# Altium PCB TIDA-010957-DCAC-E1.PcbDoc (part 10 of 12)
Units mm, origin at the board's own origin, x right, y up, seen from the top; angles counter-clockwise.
Board outline 300 x 300 mm, 4 copper layers (Top Layer, Layer 1, Layer 2, Bottom Layer), stack 1.787 mm thick; 1159 components, 619 nets, 3431 pads, 2942 vias.
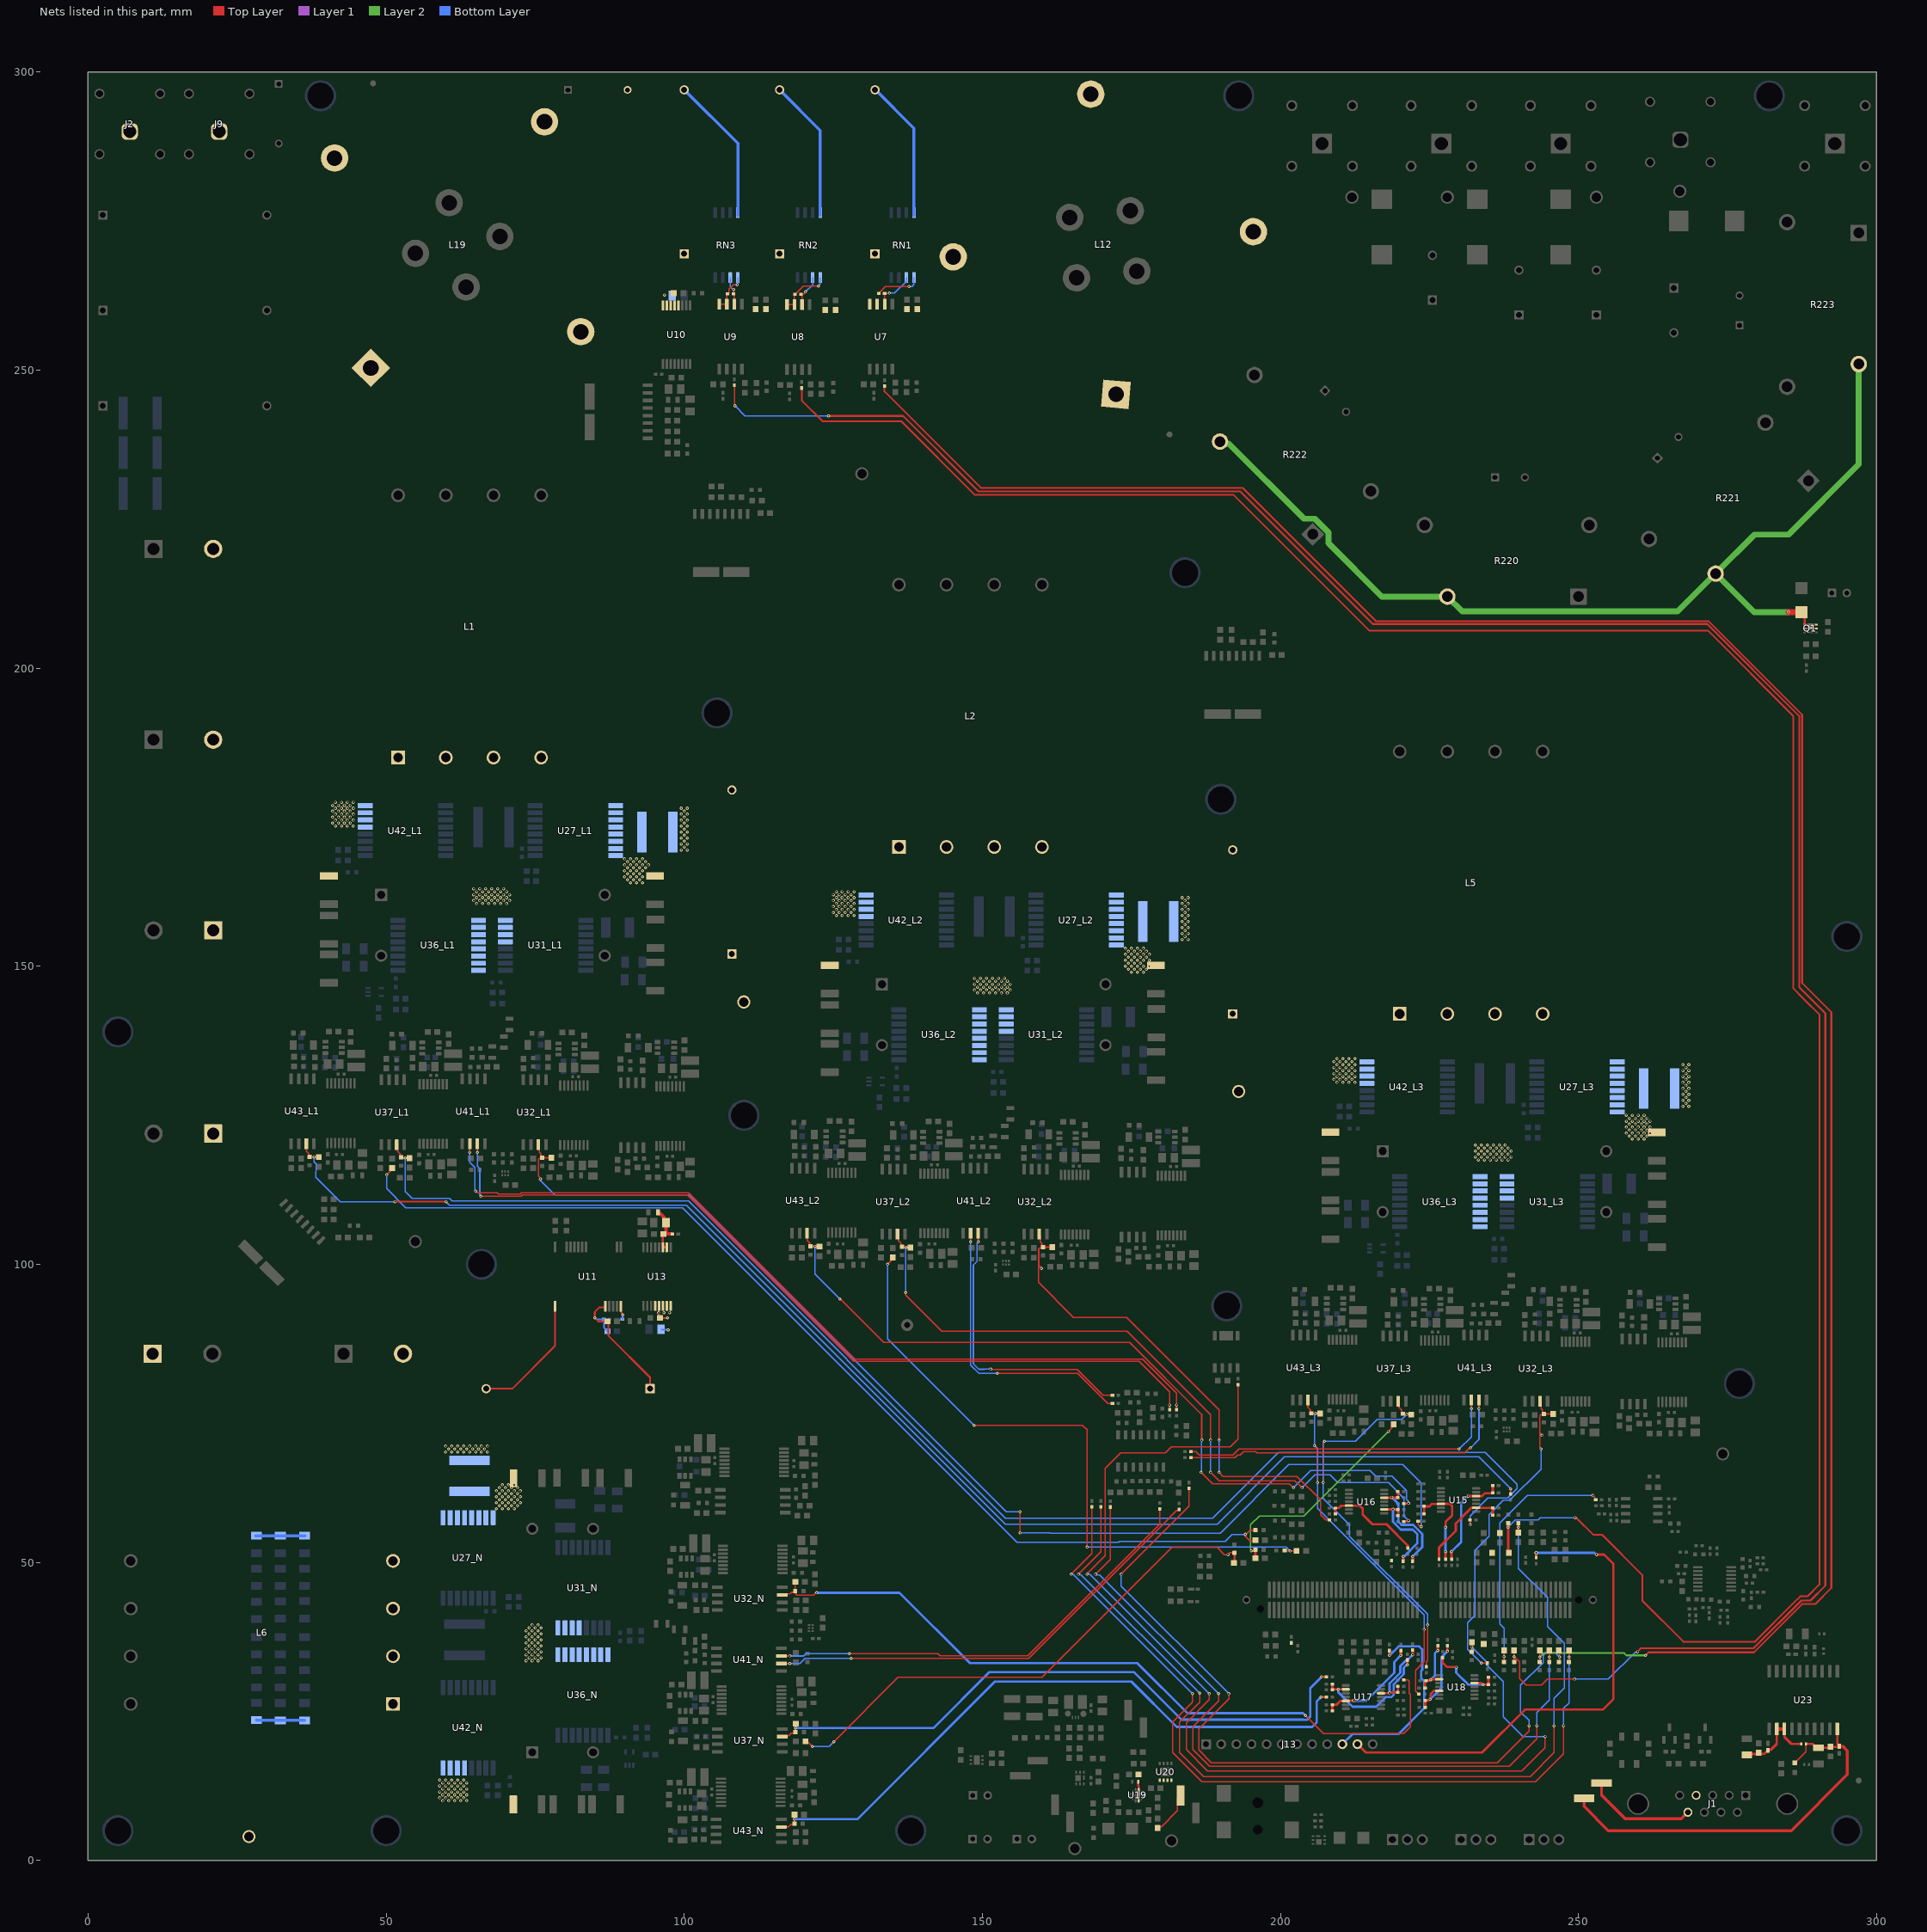
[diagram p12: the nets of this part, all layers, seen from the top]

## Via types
v1: diameter 0.508, hole 0.254, Top Layer to Bottom Layer, tented both sides, 2942 vias

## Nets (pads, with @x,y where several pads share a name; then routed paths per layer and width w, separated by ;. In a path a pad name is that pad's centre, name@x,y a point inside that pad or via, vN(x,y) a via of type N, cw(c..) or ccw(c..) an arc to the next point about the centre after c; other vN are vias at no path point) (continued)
PWM_S2_GaN_BUF_L1: C205_L1.2 R166.2 R295_L1.2 U32_L1.3 | length 197.4
  Top Layer w0.2: v1(75.9,114.3) 75.9,114.411 75.53,114.781 75.53,117.63 75.7,117.8 76.1,117.8 C205_L1.2@76.18,117.88 ; v1(156.3,58.5) 156.33,58.47 156.33,54.995 v1(156.359,54.965) ; R166.2@223.1,56.9 223.1,56.317 223.217,56.2 223.289,56.2 223.489,56 v1(223.6,56)
  Top Layer w0.254: U32_L1.3@75.545,120.05 75.718,119.877 75.718,118.794 75.957,118.555 75.957,118.103 C205_L1.2@76.18,117.88 77.733,117.88 R295_L1.2@77.75,117.863
  Bottom Layer w0.2: 75.6,114.3 78.3,111.6 100.9,111.6 154,58.5 v1(156.3,58.5) ; v1(156.359,54.965) 161.335,54.965 161.4,54.9 189.9,54.9 201.4,66.4 220.5,66.4 223.6,63.3 v1(223.6,56)
PWM_S2_GaN_BUF_L2: C205_L2.2 R178.2 R295_L2.2 U32_L2.3 | length 86.8
  Top Layer w0.2: 159.435,102.635 159.435,96.965 165.3,91.1 174.2,91.1 189.7,75.6 v1(189.7,70.5) ; v1(159.9,99.3) 159.9,99.411 159.53,99.781 159.53,102.63 159.7,102.8 160.1,102.8 C205_L2.2@160.18,102.88 ; v1(189.7,65.1) 190.4,64.4 202.8,64.4 206.7,60.5 206.7,58 207.6,57.1 R178.2@208.2,57.1
  Top Layer w0.254: U32_L2.3@159.545,105.05 159.718,104.877 159.718,103.794 159.957,103.555 159.957,103.103 C205_L2.2@160.18,102.88 161.733,102.88 R295_L2.2@161.75,102.863
  Bottom Layer w0.2: v1(189.7,65.1) v1(189.7,70.5)
PWM_S2_GaN_BUF_L3: C205_L3.2 R196.2 R295_L3.2 U32_L3.3 | length 57.6
  Top Layer w0.2: v1(233.7,33.1) R196.2@234.7,33.1 ; v1(243.7,69) 243.7,69.111 243.53,69.281 243.53,74.63 ; v1(243.9,71.3) 243.9,71.411 243.53,71.781 243.53,74.63 ; C205_L3.2@244.18,74.88 244.1,74.8 243.7,74.8 243.53,74.63
  Top Layer w0.254: U32_L3.3@243.545,77.05 243.718,76.877 243.718,75.794 243.957,75.555 243.957,75.103 C205_L3.2@244.18,74.88 245.733,74.88 R295_L3.2@245.75,74.863
  Bottom Layer w0.2: v1(233.7,33.1) 231.383,35.417 231.383,39.883 232.6,41.1 232.6,52 234.975,54.375 234.975,57.975 237.4,60.4 238.5,60.4 243.7,65.6 v1(243.7,69)
PWM_S2_GaN_BUF_N: C205_N.2 R179.2 R295_N.2 U32_N.3 | length 127.1
  Top Layer w0.2: C205_N.2@118.62,45.18 118.7,45.1 118.7,44.7 118.87,44.53 121.719,44.53 122.089,44.9 v1(122.2,44.9) ; v1(204.2,24.3) 207.239,21.261 220.661,21.261 221.6,22.2 221.6,22.234 221.805,22.439 221.805,27.851 221.6,28.055 221.6,30.1 221.4,30.3 R179.2@220.7,30.3
  Top Layer w0.254: U32_N.3@116.45,44.545 116.623,44.718 117.706,44.718 117.945,44.957 118.397,44.957 C205_N.2@118.62,45.18 118.62,46.733 R295_N.2@118.637,46.75
  Top Layer w0.4: R179.2@220.7,30.3 220.75,30.25 R179.2@220.866,30.25
  Bottom Layer w0.4: v1(122.2,44.9) 136.1,44.9 147.9,33.1 176,33.1 184.4,24.7 203.8,24.7 v1(204.2,24.3)
PWM_S2_GaN_L1: C110.1 R47.1 R171.2 U15.5 | length 15.5
  Top Layer w0.4: C110.1@224.1,58.15 224.1,59.35 224.15,59.4 225,59.4 225.4,59.8 U15.5@226.9,59.8 ; U15.5@227.102,59.802 228.464,59.802 228.8,59.466 228.8,57.9 227.705,56.805 227.705,55.905 v1(227.7,55.9) ; R47.1@227.7,50.5 v1@227.7,51.8
  Bottom Layer w0.4: v1(227.688,51.796) 227.694,51.802 227.694,55.894 v1(227.7,55.9)
PWM_S2_GaN_L2: C117.1 R55.1 R186.2 U16.5 | length 16.1
  Top Layer w0.4: R186.2@209.2,58.1 C117.1@209.2,59.1 209.25,59.15 209.85,59.15 210.2,59.5 U16.5@211,59.5 ; U16.5@212,59.5 213.3,59.5 213.8,59 213.8,58 215.4,56.4 217.8,56.4 221.35,52.85 221.35,52.45 R55.1@221.4,52.4
PWM_S2_GaN_L3: C128.1 R48.1 R201.2 U18.5 | length 13.3
  Top Layer w0.4: R48.1@227.2,34 227.2,33.2 227.96,32.44 229.46,32.44 v1(229.5,32.4) ; U18.5@232.55,29.75 233.65,29.75 233.9,29.5 v1(234,29.5) R201.2@234.9,29.5 ; R201.2@234.9,29.6 C128.1@234.9,30.7
  Bottom Layer w0.4: v1(229.5,32.4) 229.505,32.395 229.505,31.495 231.5,29.5 v1@234.1,29.5
PWM_S2_GaN_N: C122.1 R54.1 R191.2 U17.5 | length 12.9
  Top Layer w0.4: U17.5@216.866,28.052 218.252,28.052 218.4,28.2 R191.2@219.7,28.2 219.7,29.15 219.75,29.2 C122.1@219.8,29.2 ; v1(222.2,34.5) R54.1@222.2,35.3
  Bottom Layer w0.4: v1(218.3,28.1) 218.3,29.7 220.1,31.5 220.1,32.6 221.3,33.8 221.5,33.8 v1(222.2,34.5)
PWM_S3_GaN_A: J13.10 R61.1 | length 33.5
  Top Layer w0.4: v1(218.3,34.4) R61.1@218.3,35.2
  Bottom Layer w0.4: J13.10@210.39,19.5 212.09,21.2 219.8,21.2 224.105,25.505 224.105,30.095 223.6,30.6 223.6,31.744 223.805,31.948 223.805,35.395 223.3,35.9 219.8,35.9 v1(218.3,34.4)
PWM_S3_GaN_B: R80.1
PWM_S3_GaN_BUF_L1: C231_L1.2 R167.2 R305_L1.2 U37_L1.3 | length 238.4
  Top Layer w0.2: v1(231.8,56.3) R167.2@231.8,57.1
  Top Layer w0.254: U37_L1.3@51.764,120.05 51.913,119.901 51.913,118.969 52.361,118.521 52.361,118.001 52.528,117.834 v1(53.204,117.834) 53.879,117.834 R305_L1.2@53.929,117.784
  Bottom Layer w0.2: v1(53.204,117.834) 53.204,112.196 54.346,111.054 60.641,111.054 61.095,110.6 100.7,110.6 153.9,57.4 188.6,57.4 199.644,68.444 234.356,68.444 239.7,63.1 239.7,62.4 238.1,60.8 234.8,60.8 231.8,57.8 v1(231.8,56.3)
PWM_S3_GaN_BUF_L2: C231_L2.2 R180.2 R305_L2.2 U37_L2.3 | length 122.2
  Top Layer w0.2: v1(137.147,95.263) 137.147,94.822 143.185,88.784 174.316,88.784 188.3,74.8 v1(188.3,70.5) ; v1(188.3,65.1) 189.7,63.7 202.4,63.7 v1(203.6,62.5)
  Top Layer w0.254: U37_L2.3@135.764,105.05 135.913,104.901 135.913,103.969 136.361,103.521 136.361,103.001 136.528,102.834 v1(137.204,102.834) 137.879,102.834 R305_L2.2@137.929,102.784
  Top Layer w0.4: R180.2@220.7,56.85 220.75,56.9 221.3,56.9 v1@221.5,57.1
  Bottom Layer w0.2: v1(137.147,95.263) 137.175,95.292 137.175,102.805 v1(137.204,102.834) ; v1(188.3,65.1) v1(188.3,70.5) ; v1(203.6,62.5) 205.8,64.7 208.312,64.7 209.637,63.375 218.125,63.375 220.75,60.75 220.75,57.75 v1(221.5,57)
PWM_S3_GaN_BUF_L3: C231_L3.2 R197.2 R305_L3.2 U37_L3.3 | length 64.9
  Top Layer w0.2: R197.2@224.5,32.5 224.5,33.289 224.7,33.489 224.7,39.495 v1(224.705,39.5)
  Top Layer w0.254: U37_L3.3@219.764,77.05 219.913,76.901 219.913,75.969 220.361,75.521 220.361,75.001 220.528,74.834 v1(221.204,74.834) 221.879,74.834 R305_L3.2@221.929,74.784
  Layer 1 w0.2: v1(207.2,63.385) 207.2,70.1 v1(207.4,70.3)
  Bottom Layer w0.2: v1(207.2,63.385) 207.2,60.7 211.595,56.305 211.595,54.405 224.7,41.3 224.7,39.505 v1(224.705,39.5) ; v1(207.4,70.3) 212.541,70.3 216.228,73.987 220.358,73.987 v1(221.204,74.834)
PWM_S3_GaN_BUF_N: C231_N.2 R181.2 R305_N.2 U37_N.3 | length 106
  Top Layer w0.254: U37_N.3@116.45,20.764 116.599,20.913 117.531,20.913 117.979,21.361 118.499,21.361 C231_N.2@118.666,21.528 v1(118.666,22.204) 118.666,22.879 R305_N.2@118.716,22.929
  Top Layer w0.4: v1(206.9,30.8) R181.2@207.7,30.8
  Bottom Layer w0.4: v1(118.666,22.204) 141.804,22.204 151.2,31.6 175.4,31.6 183.4,23.6 203.903,23.6 203.908,23.595 204.492,23.595 204.497,23.6 204.5,23.6 205,24.1 205,28.9 v1(206.9,30.8)
PWM_S3_GaN_L1: C111.1 R49.1 R172.2 U15.9 | length 15.2
  Top Layer w0.4: R49.1@226.6,50.5 226.6,52.5 229.4,55.3 229.4,56.523 232.054,59.177 U15.9@232.2,59.177 ; U15.9@232.821,59.152 U15.9@232.821,59.152 C111.1@235.6,59.15 ; C111.1@235.6,59.15 235.6,57.95 235.65,57.9 R172.2@235.7,57.9
PWM_S3_GaN_L2: C118.1 R57.1 R187.2 U16.9 | length 15.8
  Top Layer w0.4: U16.9@217.398,58.875 C118.1@219.625,58.875 ; R187.2@219.7,57.9 C118.1@219.7,58.85 ; R57.1@220.6,50.2 v1(220.6,51)
  Bottom Layer w0.4: v1@218.9,58.9 218.888,58.888 218.888,56.812 220.2,55.5 222.2,55.5 222.95,54.75 222.95,53.19 220.799,51.04 220.64,51.04 v1(220.6,51)
  other v1: 218.888,58.896
PWM_S3_GaN_L3: C129.1 R50.1 R202.2 U18.9 | length 10
  Top Layer w0.4: C129.1@224.25,28.9 224.25,29.866 224.35,29.966 224.35,30.1 224.4,30.15 R202.2@224.45,30.15 224.5,30.2 225.1,30.2 v1(225.2,30.3) 225.3,30.4 U18.9@226.65,30.4 U18.9@226.7,30.4 ; v1(226.4,35.2) R50.1@226.4,36.1
  Bottom Layer w0.4: v1(225.2,30.3) 225.9,31 225.9,34.7 v1(226.4,35.2)
PWM_S3_GaN_N: C123.1 R56.1 R192.2 U17.9 | length 21.7
  Top Layer w0.4: C123.1@208.7,28.6 R192.2@208.7,29.6 ; C123.1@208.701,28.701 v1(209.7,28.7) U17.9@210.966,28.702 U17.9@210.966,28.702 ; v1(221.3,32.8) R56.1@221.3,33.6
  Bottom Layer w0.4: v1(209.7,28.7) 209.7,28.2 212.1,25.8 216.05,25.8 217.645,27.395 218.592,27.395 219.005,27.808 219.005,29.556 220.7,31.251 220.7,32.351 v1@221.224,32.876
PWM_S4_GaN_A: J13.11 R25.1 | length 84.5
  Top Layer w0.4: J13.11@212.93,19.5 214.33,18.1 233.8,18.1 241,25.3 254.1,25.3 255.86,27.06 255.86,49.74 254.3,51.3 v1(253,51.3) ; R25.1@242.9,50.8 v1(242.9,51.6)
  Bottom Layer w0.4: v1@242.803,51.6 252.661,51.6 252.961,51.3 v1(253,51.3)
PWM_S4_GaN_B: R60.1
PWM_S4_GaN_BUF_L1: C248_L1.2 R168.2 R322_L1.2 U43_L1.3 | length 239.8
  Top Layer w0.2: R168.2@238.6,61.5 v1(238.6,62.3)
  Top Layer w0.254: U43_L1.3@36.613,120.226 36.613,119.011 37.045,118.58 37.045,118.14 C248_L1.2@37.175,118.009 v1(37.916,118.009) 38.656,118.009 R322_L1.2@38.685,117.98 ; v1(51.5,110.5) v1(60.066,110.5)
  Bottom Layer w0.2: v1(37.916,118.009) 37.916,117.2 38.309,116.807 38.309,115.71 38.226,115.627 38.226,114.579 42.305,110.5 v1(51.5,110.5) ; v1(60.066,110.5) 60.666,109.9 100.4,109.9 153.9,56.4 189.4,56.4 200.7,67.7 233.255,67.7 238.6,62.355 v1(238.6,62.3)
PWM_S4_GaN_BUF_L2: C248_L2.2 R182.2 R322_L2.2 U43_L2.3 | length 134.3
  Top Layer w0.2: v1(186.7,65.1) 188.6,63.2 201.5,63.2 v1(202.2,62.5)
  Top Layer w0.254: U43_L2.3@120.613,105.226 120.613,104.011 121.045,103.58 121.045,103.14 C248_L2.2@121.175,103.009 v1(121.916,103.009) 122.656,103.009 R322_L2.2@122.685,102.98 ; v1(126.1,94.2) 126.156,94.2 133.456,86.9 174.704,86.9 186.8,74.804 v1(186.8,70.5)
  Top Layer w0.4: R182.2@220.7,59.85 221.55,59.85 v1@221.6,59.9
  Bottom Layer w0.2: v1(121.916,103.009) 121.916,98.384 v1(126.1,94.2) ; v1(186.7,65.1) 186.75,65.15 186.75,70.45 v1(186.8,70.5) ; v1(202.2,62.5) 205.1,65.4 215.05,65.4 215.955,64.495 218.705,64.495 221.192,62.008 221.192,60.508 221.444,60.256 221.444,59.956 v1(221.5,59.9)
PWM_S4_GaN_BUF_L3: C248_L3.2 R198.2 R322_L3.2 U43_L3.3 | length 59.6
  Top Layer w0.2: R198.2@223.2,27.9 223.15,27.9 222.65,28.4 222.65,31.91 224.095,33.355 v1(224.095,38.7)
  Top Layer w0.254: U43_L3.3@204.613,77.226 204.613,76.011 205.045,75.58 205.045,75.14 C248_L3.2@205.175,75.009 v1(205.916,75.009) 206.656,75.009 R322_L3.2@206.685,74.98
  Layer 1 w0.2: v1(205.7,69.6) 206.203,69.097 v1(206.203,63.4)
  Bottom Layer w0.2: v1(205.7,69.6) 205.729,69.629 205.729,74.739 205.916,74.925 v1(205.916,75.009) ; v1@206.2,63.397 206.2,59.055 224.095,41.16 v1(224.095,38.7)
PWM_S4_GaN_BUF_N: C248_N.2 R183.2 R322_N.2 U43_N.3 | length 110
  Top Layer w0.254: U43_N.3@116.274,5.613 117.489,5.613 117.92,6.045 118.36,6.045 C248_N.2@118.491,6.175 v1(118.491,6.916) 118.491,7.656 R322_N.2@118.52,7.685
  Top Layer w0.4: v1(206.8,27.4) R183.2@207.7,27.4
  Bottom Layer w0.4: v1(118.491,6.916) 129.016,6.916 152.1,30 175,30 182.6,22.4 205.3,22.4 206.1,23.2 206.1,26.7 v1(206.8,27.4)
PWM_S4_GaN_L1: C112.1 R45.1 R173.2 U15.12 | length 17.5
  Top Layer w0.4: R45.1@228.7,50.5 v1@228.7,51.9 ; v1(231.5,61.1) 231.501,61.101 U15.12@232.821,61.102 232.831,61.111 233.811,61.111 234.3,61.6 C112.1@235.6,61.6 ; C112.1@235.6,61.65 R173.2@235.6,62.9
  Bottom Layer w0.4: v1(228.688,51.796) 230.327,53.435 230.327,60.027 v1@231.5,61.2
PWM_S4_GaN_L2: C119.1 R53.1 R188.2 U16.12 | length 17.9
  Top Layer w0.4: U16.12@217.398,60.825 217.408,60.835 R188.2@219.635,60.835 ; C119.1@219.6,61.9 219.7,61.8 R188.2@219.7,60.85 ; R53.1@222.2,50.2 v1(222.2,51)
  Bottom Layer w0.4: v1@218.7,60.9 218.7,60.883 219.8,59.783 219.8,56.8 220.3,56.3 222.249,56.3 223.771,54.777 223.771,52.572 v1(222.2,51)
  other v1: 218.688,60.896
PWM_S4_GaN_L3: C130.1 R46.1 R203.2 U18.12 | length 14.6
  Top Layer w0.4: R203.2@224.294,26.83 224.344,26.88 224.944,26.88 v1@225.194,27.13 ; C130.1@224.3,25.9 R203.2@224.3,26.824 ; v1@225.2,27.1 225.2,27.886 225.755,28.44 226.64,28.44 U18.12@226.65,28.45 ; v1(228,35.1) R46.1@228,36
  Bottom Layer w0.4: v1@225.1,27 227,28.9 227,34.1 v1(228,35.1)
  other v1: 225.094,27.03
PWM_S4_GaN_N: C124.1 R58.1 R193.2 U17.12 | length 17.1
  Top Layer w0.4: C124.1@208.7,25.2 R193.2@208.7,26.1 209.4,26.1 210.043,26.743 210.957,26.743 U17.12@210.966,26.752 ; U17.12@211.6,26.777 212.277,26.777 v1(212.3,26.8) ; v1(220.2,34.4) R58.1@220.2,35.2
  Bottom Layer w0.4: v1(212.3,26.8) 214.414,26.8 219.1,31.486 219.1,33.3 v1(220.2,34.4)
SN_L1: L1.1 L1.2 L1.3 L1.4 U31_L1.13 U31_L1.14 U31_L1.15 U31_L1.16 U36_L1.1 U36_L1.2 U36_L1.3 U36_L1.4 U36_L1.5 U36_L1.6 U36_L1.7 U36_L1.8
  other v1: 65.2,160.5 66.2,160.5 67.2,160.5 68.2,160.5 69.2,160.5 70.2,160.5 64.7,161 65.7,161 66.7,161 67.7,161 68.7,161 69.7,161 70.7,161 65.2,161.5 66.2,161.5 67.2,161.5 68.2,161.5 69.2,161.5 70.2,161.5 64.7,162 65.7,162 66.7,162 67.7,162 68.7,162 69.7,162 70.7,162 65.2,162.5 66.2,162.5 67.2,162.5 68.2,162.5 69.2,162.5 70.2,162.5 64.7,163 65.7,163 66.7,163 67.7,163 68.7,163 69.7,163
SN_L2: L2.1 L2.2 L2.3 L2.4 U31_L2.13 U31_L2.14 U31_L2.15 U31_L2.16 U36_L2.1 U36_L2.2 U36_L2.3 U36_L2.4 U36_L2.5 U36_L2.6 U36_L2.7 U36_L2.8
  other v1: 149.2,145.5 150.2,145.5 151.2,145.5 152.2,145.5 153.2,145.5 154.2,145.5 148.7,146 149.7,146 150.7,146 151.7,146 152.7,146 153.7,146 154.7,146 149.2,146.5 150.2,146.5 151.2,146.5 152.2,146.5 153.2,146.5 154.2,146.5 148.7,147 149.7,147 150.7,147 151.7,147 152.7,147 153.7,147 154.7,147 149.2,147.5 150.2,147.5 151.2,147.5 152.2,147.5 153.2,147.5 154.2,147.5 148.7,148 149.7,148 150.7,148 151.7,148 152.7,148 153.7,148
SN_L3: L5.1 L5.2 L5.3 L5.4 U31_L3.13 U31_L3.14 U31_L3.15 U31_L3.16 U36_L3.1 U36_L3.2 U36_L3.3 U36_L3.4 U36_L3.5 U36_L3.6 U36_L3.7 U36_L3.8
  other v1: 233.2,117.5 234.2,117.5 235.2,117.5 236.2,117.5 237.2,117.5 238.2,117.5 232.7,118 233.7,118 234.7,118 235.7,118 236.7,118 237.7,118 238.7,118 233.2,118.5 234.2,118.5 235.2,118.5 236.2,118.5 237.2,118.5 238.2,118.5 232.7,119 233.7,119 234.7,119 235.7,119 236.7,119 237.7,119 238.7,119 233.2,119.5 234.2,119.5 235.2,119.5 236.2,119.5 237.2,119.5 238.2,119.5 232.7,120 233.7,120 234.7,120 235.7,120 236.7,120 237.7,120
SN_LN: L6.1 L6.2 L6.3 L6.4 U31_N.13 U31_N.14 U31_N.15 U31_N.16 U36_N.1 U36_N.2 U36_N.3 U36_N.4 U36_N.5 U36_N.6 U36_N.7 U36_N.8
  other v1: 73.5,33.5 74.5,33.5 75.5,33.5 74,34 75,34 76,34 73.5,34.5 74.5,34.5 75.5,34.5 74,35 75,35 76,35 73.5,35.5 74.5,35.5 75.5,35.5 74,36 75,36 76,36 73.5,36.5 74.5,36.5 75.5,36.5 74,37 75,37 76,37 73.5,37.5 74.5,37.5 75.5,37.5 74,38 75,38 76,38 73.5,38.5 74.5,38.5 75.5,38.5 74,39 75,39 76,39 74.5,39.5 75.5,39.5
SN_Relays: D3.2 Q1.1 Q1.2 Q1.5 Q1.6 Q1.8 R220.2 R221.2 R222.2 R223.2 | length 169.1
  Top Layer w0.3: Q1.2@287.93,206.65 288.58,206.65 Q1.8@288.905,206.975 ; D3.2@287.93,208.7 Q1.1@287.93,207.3 288.58,207.3 Q1.8@288.905,206.975 ; Q1.8@289.15,206.65 Q1.5@289.88,206.65 ; Q1.6@289.8,207.3 289.23,207.3 Q1.8@288.905,206.975
  Top Layer w1: v1(285.2,209.4) D3.2@287.1,209.4
  Layer 2 w1: R222.2@189.863,238.005 190.198,237.67 191.33,237.67 203.929,225.071 205.732,225.071 208.041,222.762 208.041,220.959 217,212 R220.2@228,212 230.5,209.5 266.632,209.5 R221.2@272.995,215.863 ; v1(285.2,209.4) 279.458,209.4 R221.2@272.995,215.863 ; R223.2@296.9,250.9 297,250.8 297,234.2 285.2,222.4 279.532,222.4 R221.2@272.995,215.863
T_HEATSINK_DCAC: C14.1 R19.1 R42.1 | length 181.3
  Top Layer w0.2: v1@167.535,48.035 170.6,51.1 170.6,65.8 173.2,68.4 180.7,68.4 181.7,69.4 191.6,69.4 192.9,70.7 R19.1@192.9,79.8 ; v1(188.044,27.956) 188.044,26.944 184.2,23.1 184.2,18.6 187.8,15 240.5,15 244.4,18.9 v1(244.4,20.805) ; C14.1@232.1,35 v1(232.1,35.8) R42.1@232.1,36.6
  Bottom Layer w0.2: v1(167.543,48.026) 167.555,48.014 167.986,48.014 v1(188.044,27.956) ; v1(232.1,35.8) 234.495,33.405 234.495,32.905 237.405,29.995 237.405,24.095 240.695,20.805 v1(244.4,20.805)
TEMP_S3_GaN_ISO_L1: C230_L1.2 R74.2 R302_L1.1 | length 177.4
  Top Layer w0.2: v1(50.1,115) 50.911,115.811 50.911,116.066 R302_L1.1@51,116.155 ; R74.2@195.789,53.441 195.63,53.6 194.9,53.6 194.142,54.358 194.142,54.658 v1(194.1,54.7) 194.183,54.7 194.883,55.4 C230_L1.2@195.89,55.4
  Bottom Layer w0.2: v1(50.1,115) 50.1,112.7 53.3,109.5 99.7,109.5 155.805,53.395 172.872,53.395 172.977,53.5 190.7,53.5 191.9,54.7 v1(194.1,54.7)
TEMP_S3_GaN_ISO_L2: C230_L2.2 R75.2 R302_L2.1 | length 109.8
  Top Layer w0.2: v1(134.1,100) 134.911,100.811 134.911,101.066 R302_L2.1@135,101.155 ; v1(148.625,72.987) 166.813,72.987 167.561,72.239 v1(167.561,52.54) ; C230_L2.2@200.7,51.9 v1(201.6,51.9) R75.2@202.7,51.9
  Bottom Layer w0.2: v1(134.1,100) 134.1,87.512 v1(148.625,72.987) ; v1(167.561,52.54) 189.157,52.54 189.175,52.558 200.942,52.558 v1(201.6,51.9)
TEMP_S3_GaN_ISO_L3: C230_L3.2 R76.2 R302_L3.1 | length 37.5
  Top Layer w0.2: v1(195.09,51.924) 195.691,51.924 C230_L3.2@195.786,52.019 ; v1(218.1,72) 218.911,72.811 218.911,73.066 R302_L3.1@219,73.155
  Top Layer w0.4: R76.2@195.8,50.7 C230_L3.2@195.8,51.9
  Layer 2 w0.2: v1(195.09,51.924) 195.031,51.983 195.031,52.164 195,52.195 195,56.3 196.463,57.763 203.918,57.763 218.1,71.945 v1(218.1,72)
TEMP_S3_GaN_ISO_N: C230_N.2 R77.2 R302_N.1 | length 88.2
  Top Layer w0.2: R302_N.1@120.345,20 120.434,19.911 120.689,19.911 v1(121.5,19.1) ; v1(125.089,19.911) 135.877,30.7 160,30.7 181.8,52.5 189.4,52.5 190.6,51.3 v1@191.1,51.3 ; v1(191.2,51.3) 191.5,51.6 C230_N.2@192.3,51.6
  Top Layer w0.4: R77.2@192.2,49.9 192.3,50 C230_N.2@192.3,51.3
  Bottom Layer w0.2: v1@121.392,19.1 v1(121.5,19.1) 124.277,19.1 v1(125.089,19.911)
V_FC_L1: C96.1 R31.2 R146.2 | length 162.3
  Top Layer w0.2: v1(166.1,48) 169.9,51.8 R146.2@169.9,59.3 ; v1(186.455,28.045) 186.455,26.555 183.1,23.2 183.1,18.1 187.1,14.1 241.9,14.1 245.9,18.1 v1(245.9,22.6)
  Top Layer w0.4: R31.2@239.9,55 v1(239.9,55.9) C96.1@239.9,56.6 C96.1@239.9,56.7
  Bottom Layer w0.2: v1(166.1,48) 166.128,47.972 166.528,47.972 v1(186.455,28.045) ; v1(239.9,55.9) 239.9,49 244.795,44.105 244.795,39.205 247.6,36.4 247.6,28.9 245.9,27.2 v1(245.9,22.6)
V_FC_L2: C99.1 R22.2 R151.2 | length 140.7
  Top Layer w0.2: v1(164.9,48) 168.4,51.5 R151.2@168.4,59.3 ; v1(185.215,27.985) 185.215,26.515 181.9,23.2 181.9,18.1 186.8,13.2 242.8,13.2 247.5,17.9 v1(247.5,22.6) ; C99.1@248.4,33.3 v1(248.4,34.1) R22.2@248.4,35.2
  Bottom Layer w0.2: v1(164.9,48) 164.978,47.922 165.278,47.922 v1(185.215,27.985) ; v1(247.5,22.6) 247.5,25.505 248.4,26.405 v1(248.4,34.1)
V_FC_L3: C102.1 R27.2 R156.2 | length 129.6
  Top Layer w0.2: v1(169,48) 171.478,50.478 171.478,59.253 R156.2@171.457,59.275 ; v1(189.63,27.97) 189.63,26.73 185.3,22.4 185.3,18.6 188.1,15.8 238.4,15.8 243,20.4 v1(243,22.6) ; C102.1@245.1,33.3 v1(245.1,34.1) R27.2@245.1,35.2
  Bottom Layer w0.2: v1(169,48) 169.078,47.922 169.678,47.922 v1(189.63,27.97) ; v1(243,22.6) 243,24.8 245.1,26.9 v1(245.1,34.1)
V_FC_N: C105.1 R24.2 R161.2 | length 136.6
  Top Layer w0.2: v1(173.3,48) 184.7,59.4 R161.2@184.7,62.4 ; v1(191.345,27.955) 191.345,27.145 186.3,22.1 186.3,18.5 188.4,16.4 236.4,16.4 241.7,21.7 v1(241.7,22.6) ; C105.1@246.7,33.3 246.8,33.4 v1(246.8,34.1) 246.8,35.1 R24.2@246.7,35.2
  Bottom Layer w0.2: v1(173.3,48) 173.3,46 v1(191.345,27.955) ; v1(241.7,22.6) 241.7,23.505 240.3,24.905 240.3,29.4 244.105,33.205 244.105,34.405 244.5,34.8 246.1,34.8 v1(246.8,34.1)
V_FC_NEG_L1: R147.2 U41_L1.6 | length 142.9
  Top Layer w0.2: v1(65,112.3) 65.027,112.3 65.327,112 65.645,112 65.649,112.005 68.64,112.005 68.849,111.795 72.498,111.795 72.703,112 100.7,112 128.6,84.1 176.9,84.1 182.6,78.4 v1(182.6,76.4) 182.595,76.395 182.595,75.614 R147.2@182.59,75.609
  Top Layer w0.254: v1(64.034,118.791) U41_L1.6@64.034,120.208
  Bottom Layer w0.2: 64.9,112.622 64.922,112.6 64.922,112.378 v1(65,112.3)
  Bottom Layer w0.254: v1(64.034,118.791) 64.034,117.089 64.9,116.222 64.9,113.958 64.9,112.622
V_FC_NEG_L2: R152.2 U41_L2.6 | length 50.3
  Top Layer w0.2: v1(152.5,81.7) 166,81.7 171.018,76.682 171.802,76.682 R152.2@171.82,76.663
  Top Layer w0.254: v1(148.034,103.791) U41_L2.6@148.034,105.208
  Bottom Layer w0.254: 148.034,102.089 v1(148.034,103.791) 148.034,83.1 149.434,81.7 v1(152.5,81.7)
V_FC_NEG_L3: R157.2 U41_L3.6 | length 54.7
  Top Layer w0.2: R157.2@185,68.6 185.8,68.6 186.4,68 192,68 193,69 193.679,69 193.684,69.005 196.027,69.005 196.031,69 229.941,69 v1(229.943,68.998)
  Top Layer w0.254: v1(232.034,75.791) U41_L3.6@232.034,77.208
  Bottom Layer w0.254: v1(229.943,68.998) 229.971,68.998 232.034,71.061 v1(232.034,75.791)
V_FC_NEG_N: R162.2 U41_N.6 | length 77.5
  Top Layer w0.2: v1(128,33.9) 157.8,33.9 180.165,56.265 182.6,58.7 182.85,58.7 183,58.85 R162.2@183,58.9
  Top Layer w0.254: U41_N.6@116.292,33.034 v1(117.709,33.034)
  Bottom Layer w0.254: v1(117.709,33.034) 119.411,33.034 120.278,33.9 v1(128,33.9)
V_FC_POS_L1: R145.2 U41_L1.7 | length 141.4
  Top Layer w0.2: v1(65.9,111.4) 65.905,111.395 72.664,111.395 72.869,111.6 100.5,111.6 128.4,83.7 176.3,83.7 181.4,78.6 v1(181.4,76.4) 181.414,76.386 181.414,75.618 R145.2@181.428,75.604
  Top Layer w0.254: v1(65.304,118.782) 65.304,119.746 65.178,119.872 65.178,120.082 U41_L1.7@65.304,120.208
  Bottom Layer w0.254: v1(65.304,118.782) 65.304,116.463 65.7,116.067 65.7,111.696 65.9,111.496 v1(65.9,111.4)
V_FC_POS_L2: R150.2 U41_L2.7 | length 47.9
  Top Layer w0.2: v1(151.4,82.4) 151.478,82.322 165.944,82.322 170.266,78 R150.2@171.82,78
  Top Layer w0.254: v1(149.304,103.782) 149.304,104.746 149.178,104.872 149.178,105.082 U41_L2.7@149.304,105.208
  Bottom Layer w0.2: 150.402,82.4 v1(151.4,82.4)
  Bottom Layer w0.254: v1(149.304,103.782) 149.304,103.715 149.1,103.511 149.1,100.488 148.5,99.888 148.5,83.3 149.4,82.4 150.402,82.4
V_FC_POS_L3: R155.2 U41_L3.7 | length 56.4
  Top Layer w0.2: R155.2@185,67.6 192.4,67.6 192.8,68 193.245,68 193.849,68.605 195.861,68.605 196.066,68.4 230.883,68.4 231.604,69.122 231.822,69.122 v1(231.9,69.2)
  Top Layer w0.254: v1(233.304,75.782) 233.304,76.746 233.178,76.872 233.178,77.082 U41_L3.7@233.304,77.208
  Bottom Layer w0.254: v1(231.9,69.2) 233.297,70.597 233.297,73.635 ; 233.304,73.642 v1(233.304,75.782)
V_FC_POS_N: R160.2 U41_N.7 | length 75.6
  Top Layer w0.2: v1(127.7,34.7) 142.523,34.7 142.923,34.3 157.634,34.3 179.765,56.43 R160.2@179.765,58.975
  Top Layer w0.254: U41_N.7@116.292,34.304 116.418,34.178 116.628,34.178 116.754,34.304 v1(117.718,34.304)
  Bottom Layer w0.254: v1(117.718,34.304) 120.037,34.304 120.433,34.7 v1(127.7,34.7)
V_PCC_IN1: C58.1 RN1.6 U7.2 | length 6.9
  Top Layer w0.2: U7.2@133.64,261.05 133.64,262.83 C58.1@133.62,262.85 133.645,262.875 134.375,262.875 v1(134.4,262.9)
  Bottom Layer w0.2: v1(134.4,262.9) 135.27,262.9 137.27,264.9 RN1.6@137.27,265.5
V_PCC_IN2: C65.1 RN2.6 U8.2 | length 5.6
  Top Layer w0.2: U8.2@119.77,261 119.77,262.499 119.77,262.549 119.62,262.699 C65.1@119.57,262.699 119.679,262.808 120.035,262.808 120.346,263.118 v1@120.351,263.118
  Bottom Layer w0.2: v1(120.357,263.118) 121.54,264.301 RN2.6@121.54,265.5
V_PCC_IN3: C72.1 RN3.6 U9.2 | length 4.8
  Top Layer w0.2: v1(108.269,263.508) 108.269,262.801 C72.1@108.27,262.799 108.405,262.664 U9.2@108.405,261.05
  Bottom Layer w0.2: RN3.6@107.73,265.5 107.73,263.97 108.192,263.508 v1(108.269,263.508)
V_PCC_L1: C20.2 L12.1 L19.1 RN1.4 | length 23.9
  Bottom Layer w0.5: C20.2@132,297.083 138.54,290.543 RN1.4@138.54,275.9
V_PCC_L2: C21.2 L12.3 L19.3 RN2.4 | length 24.5
  Bottom Layer w0.5: C21.2@116,297.53 C21.2@116,297 122.81,290.19 RN2.4@122.81,275.9
V_PCC_L3: C22.2 L12.5 L19.5 RN3.4 | length 24.8
  Bottom Layer w0.5: C22.2@100,297 109,288 RN3.4@109,275.9
V_PCC_N: C20.1 C21.1 C22.1 C25.2 C54.2 C55.1 C58.2 C61.2 C62.1 C65.2 C68.2 C69.1 C72.2 C75.2 C76.2 L12.7 L19.7 RN1.5 RN2.5 RN3.5 U7.3 U7.4 U8.3 U8.4 U9.3 U9.4 U10.12 U10.13 U10.14 U10.15 U10.16 | length 23.7
  Top Layer w0.2: U9.4@105.865,261.05 U9.3@107.135,261.05 107.135,262.664 C72.2@107.27,262.799 107.32,262.799 107.47,262.949 107.47,263.565 108.205,264.3 v1(108.9,264.3) ; U8.4@117.23,261 U8.3@118.5,261 118.5,262.629 C65.2@118.57,262.699 118.62,262.699 118.97,263.049 118.97,263.073 119.997,264.1 v1(122.5,264.1) ; C58.2@132.62,262.85 132.67,262.85 132.82,263 132.82,263.05 133.77,264 v1(137.7,264)
  Bottom Layer w0.2: v1(108.9,264.3) 109,264.4 RN3.5@109,265.5 ; v1(122.5,264.1) 122.81,264.41 RN2.5@122.81,265.5 ; v1(137.7,264) 138.2,264 138.54,264.34 RN1.5@138.54,265.5
  other v1: 96.7,262.6
V_SENSE_1: R36.2
V_SENSE_2: R37.2
V_SENSE_3: R41.1
V_SENSE_DC: C84.1 R35.1 R140.2 | length 43
  Top Layer w0.2: C84.1@237.5,33.3 v1(237.5,34.2) R35.1@237.5,35.2 ; v1(252.4,61.2) 252.727,60.873 252.727,60.647 R140.2@252.897,60.477
  Bottom Layer w0.2: v1(237.5,34.2) 237.5,38.978 236.795,39.683 236.795,56.595 241.4,61.2 v1(252.4,61.2)
V_SENSE_PCC_L1: C59.2 R28.2 R130.2 | length 381.7
  Top Layer w0.2: C59.2@243.5,33.3 v1(243.5,34.1) R28.2@243.5,35.2
  Top Layer w0.3: R130.2@133.6,247.3 133.6,246.4 149.746,230.254 193.646,230.254 216,207.9 271.807,207.9 287.504,192.203 287.504,147.196 291.2,143.5 292.4,142.3 292.4,45.7 289.704,43.004 287.504,43.004 279.4,34.9 261.745,34.9 v1(261.248,34.403)
  Layer 2 w0.2: v1@261.24,34.395 v1(261.248,34.403)
  Layer 2 w0.3: v1(243.5,34.1) 244.2,34.8 257.623,34.8 258.028,34.395 v1@261.24,34.395
V_SENSE_PCC_L2: C66.2 R33.2 R132.2 | length 410.9
  Top Layer w0.3: R132.2@119.705,246.994 119.705,244.895 123.2,241.4 136.4,241.4 148.709,229.091 192.109,229.091 214.9,206.3 271.7,206.3 286,192 286,146.3 287.9,144.4 290.4,141.9 290.4,46.3 288.4,44.3 287.2,44.3 286,43.1 279.6,36.7 267.6,36.7 260.7,43.6 260.7,47.9 254,54.6 252.5,54.6 249.6,57.5 v1(249.4,57.5)
  Top Layer w0.4: C66.2@238.2,56.6 238.2,51.7 R33.2@238.3,51.6
  Bottom Layer w0.2: v1(238.188,55.896) 239.392,57.1 243.2,57.1 243.6,57.5 v1(249.4,57.5)
V_SENSE_PCC_L3: C73.2 R34.1 R134.2 | length 415.9
  Top Layer w0.2: R134.2@108.405,247.445 108.452,247.397 108.452,244.048 v1(108.5,244) ; C73.2@239.2,33.3 v1(239.2,34.2) ; R34.1@239.2,35.2 v1(239.2,34.2) ; v1(249.32,30.4) 244.8,30.4 243.8,29.4 241.2,29.4 240.1,30.5 240.1,33.3 v1(239.2,34.2)
  Top Layer w0.3: v1(124.2,242.3) 136.7,242.3 149.351,229.649 193.251,229.649 215.5,207.4 271.6,207.4 287.004,191.996 287.004,146.496 291.4,142.1 291.4,46.1 288.9,43.6 287.393,43.6 279.393,35.6 260.5,35.6 v1(259.9,35)
  Bottom Layer w0.2: v1(108.5,244) 110.2,242.3 v1(124.2,242.3) ; v1(249.32,30.4) 255,30.4 259.522,34.922 259.822,34.922 v1(259.9,35)
VDC+: C1.2 C2.2 C3.2 C10.2 C11.2 C12.2 C217_L1.1 C217_L2.1 C217_L3.1 C217_N.1 D7_L1.1 D7_L2.1 D7_L3.1 D7_N.1 J2.1 R1.2 R2.2 R3.2 U11.1 U27_L1.1 U27_L1.2 U27_L1.3 U27_L1.4 U27_L1.5 U27_L1.6 U27_L1.7 U27_L1.8 U27_L2.1 U27_L2.2 U27_L2.3 U27_L2.4 U27_L2.5 U27_L2.6 U27_L2.7 U27_L2.8 U27_L3.1 U27_L3.2 U27_L3.3 U27_L3.4 U27_L3.5 U27_L3.6 U27_L3.7 U27_L3.8 U27_N.1 U27_N.2 U27_N.3 U27_N.4 U27_N.5 U27_N.6 U27_N.7 U27_N.8 | length 29.1
  Top Layer w0.3: C10.2@66.779,79.135 71.135,79.135 78.329,86.329 U11.1@78.329,92.954
  Bottom Layer w0.5: R3.2@28.1,54.45 R2.2@31.95,54.45 ; R2.2@32.1,54.45 R1.2@35.95,54.45 ; R1.2@36.1,54.45 R1.2@36.375,54.45
  other v1: 68.5,59 69.5,59 70.5,59 71.5,59 69,59.5 70,59.5 71,59.5 72,59.5 68.5,60 69.5,60 70.5,60 71.5,60 72.5,60 69,60.5 70,60.5 71,60.5 72,60.5 68.5,61 69.5,61 70.5,61 71.5,61 72.5,61 69,61.5 70,61.5 71,61.5 72,61.5 68.5,62 69.5,62 70.5,62 71.5,62 72.5,62 69,62.5 70,62.5 71,62.5 72,62.5 69.5,63 70.5,63 71.5,63 259,121 260,121 261,121 258.5,121.5 259.5,121.5 260.5,121.5 261.5,121.5 258,122 259,122 260,122 261,122 262,122 258.5,122.5 259.5,122.5 260.5,122.5 261.5,122.5 258,123 259,123 260,123 261,123 262,123 258.5,123.5 259.5,123.5 260.5,123.5 261.5,123.5 258,124 259,124 260,124 261,124 262,124 258.5,124.5 259.5,124.5 260.5,124.5 261.5,124.5 258,125 259,125 260,125 261,125 175,149 176,149 177,149 174.5,149.5 175.5,149.5 176.5,149.5 177.5,149.5 174,150 175,150 176,150 177,150 178,150 174.5,150.5 175.5,150.5 176.5,150.5 174,151 175,151 176,151 177,151 178,151 174.5,151.5 175.5,151.5 176.5,151.5 177.5,151.5 174,152 175,152 176,152 177,152 178,152 174.5,152.5 175.5,152.5 176.5,152.5 177.5,152.5 174,153 175,153 176,153 177,153 91,164 92,164 93,164 90.5,164.5 91.5,164.5 92.5,164.5 90,165 91,165 92,165 93,165 90.5,165.5 91.5,165.5 92.5,165.5 90,166 91,166 92,166 93,166 90.5,166.5 91.5,166.5 92.5,166.5 93.5,166.5 90,167 91,167 92,167 93,167 94,167 90.5,167.5 91.5,167.5 92.5,167.5 93.5,167.5 90,168 91,168 92,168 93,168
VDC-_REF: C7.1 C8.1 C9.1 C10.1 C11.1 C12.1 C85.1 C87.1 C88.2 C89.2 C90.2 C217_L1.2 C217_L2.2 C217_L3.2 C217_N.2 D14_L1.2 D14_L2.2 D14_L3.2 D14_N.2 J9.1 R16.1 R17.1 R18.1 R138.2 TP8.1 TP9.1 TP10.1 U11.2 U11.6 U13.12 U13.13 U13.14 U13.15 U13.16 U42_L1.13 U42_L1.14 U42_L1.15 U42_L1.16 U42_L2.13 U42_L2.14 U42_L2.15 U42_L2.16 U42_L3.13 U42_L3.14 U42_L3.15 U42_L3.16 U42_N.13 U42_N.14 U42_N.15 U42_N.16 | length 37.2
  Top Layer w0.3: U11.2@86.8,92.8 85.8,92.8 85,92 v1(85,91) 85.582,90.418 C88.2@87.129,90.418 ; C88.2@87.093,90.3 87.3,90.093 87.3,88 94.279,81.021 C10.1@94.279,79.135 ; U11.6@89.312,92.112 89.5,91.925 89.5,91.784 89.7,91.584 v1(89.7,91.5) ; U13.13@95.7,92.8 95.7,91.246 C90.2@95.913,91.033 ; C90.2@95.9,91 v1(97.2,91)
  Bottom Layer w0.3: v1(85,91) 85.084,91 85.315,90.768 R138.2@86.529,90.768 86.568,90.768 R138.2@86.6,90.8 ; R138.2@86.529,90.668 86.529,89.398 86.779,89.148 86.779,89.123 87.104,88.798 C87.1@87.129,88.798 ; C85.1@89.629,90.768 89.665,90.804 89.665,91.465 v1(89.7,91.5) ; C89.2@96.2,89 v1(97.3,89)
  Bottom Layer w0.5: R18.1@28.248,23.55 28.275,23.523 R17.1@31.977,23.523 ; R17.1@32.119,23.496 R16.1@36.323,23.496
  other v1: 59.5,10 60.5,10 61.5,10 62.5,10 63.5,10 59,10.5 60,10.5 61,10.5 62,10.5 63,10.5 59.5,11 60.5,11 61.5,11 62.5,11 63.5,11 59,11.5 60,11.5 61,11.5 62,11.5 63,11.5 59.5,12 60.5,12 61.5,12 62.5,12 63.5,12 59,12.5 60,12.5 61,12.5 62,12.5 63,12.5 59.5,13 60.5,13 61.5,13 62.5,13 63.5,13 59,13.5 60,13.5 61,13.5 62,13.5 63,13.5 60,68.5 61,68.5 62,68.5 63,68.5 64,68.5 65,68.5 66,68.5 67,68.5 60.5,69 61.5,69 62.5,69 63.5,69 64.5,69 65.5,69 66.5,69 60,69.5 61,69.5 62,69.5 63,69.5 64,69.5 65,69.5 66,69.5 67,69.5 95.709,91.851 96.586,91.882 97.532,91.906 267.5,126.5 268.5,126.5 268,127 267.5,127.5 268.5,127.5 268,128 267.5,128.5 268.5,128.5 268,129 267.5,129.5 268.5,129.5 268,130 209.5,130.5 210.5,130.5 211.5,130.5 212.5,130.5 267.5,130.5 268.5,130.5 209,131 210,131 211,131 212,131 268,131 209.5,131.5 210.5,131.5 211.5,131.5 212.5,131.5 267.5,131.5 268.5,131.5 209,132 210,132 211,132 212,132 268,132 209.5,132.5 210.5,132.5 211.5,132.5 212.5,132.5 267.5,132.5 268.5,132.5 209,133 210,133 211,133 212,133 268,133 209.5,133.5 210.5,133.5 211.5,133.5 212.5,133.5 267.5,133.5 268.5,133.5 209,134 210,134 211,134 212,134 209.5,134.5 210.5,134.5 211.5,134.5 212.5,134.5 183.5,154.5 184.5,154.5 184,155 183.5,155.5 184.5,155.5 184,156 183.5,156.5 184.5,156.5 184,157 183.5,157.5 184.5,157.5 184,158 125.5,158.5 126.5,158.5 127.5,158.5 128.5,158.5 183.5,158.5 184.5,158.5 125,159 126,159 127,159 128,159 184,159 125.5,159.5 126.5,159.5 127.5,159.5 128.5,159.5 183.5,159.5 184.5,159.5 125,160 126,160 127,160 128,160 184,160 125.5,160.5 126.5,160.5 127.5,160.5 128.5,160.5 183.5,160.5 184.5,160.5 125,161 126,161 127,161 128,161 184,161 125.5,161.5 126.5,161.5 127.5,161.5 128.5,161.5 183.5,161.5 184.5,161.5 125,162 126,162 127,162 128,162 125.5,162.5 126.5,162.5 127.5,162.5 128.5,162.5 99.5,169.5 100.5,169.5 100,170 99.5,170.5 100.5,170.5 100,171 99.5,171.5 100.5,171.5 100,172 99.5,172.5 100.5,172.5 100,173 41.5,173.5 42.5,173.5 43.5,173.5 44.5,173.5 99.5,173.5 100.5,173.5 41,174 42,174 43,174 44,174 100,174 41.5,174.5 42.5,174.5 43.5,174.5 44.5,174.5 99.5,174.5 100.5,174.5 41,175 42,175 43,175 44,175 100,175 41.5,175.5 42.5,175.5 43.5,175.5 44.5,175.5 99.5,175.5 100.5,175.5 41,176 42,176 43,176 44,176 100,176 41.5,176.5 42.5,176.5 43.5,176.5 44.5,176.5 99.5,176.5 100.5,176.5 41,177 42,177 43,177 44,177 41.5,177.5 42.5,177.5 43.5,177.5 44.5,177.5
VIN_PWR: C131.1 C132.1 J14.2 R204.2 U19.5 U20.1 U20.2 U20.3 U20.4 | length 9.6
  Top Layer w0.2: R204.2@179.391,5.446 179.594,5.649 180.049,5.649 182.733,8.333 182.733,10.351 J14.2@183.268,10.886
  Top Layer w0.3: C132.1@176.159,13.186 176.159,12.513 176.229,12.444 U19.5@176.229,10.925
VIN_PWR_CAN: J1.4
VINP_DC-_HAVOK: C91.1 C92.1 L9.1 R143.1 U13.2 U13.3 | length 8.9
  Top Layer w0.2: C91.1@96.413,104.988 96.525,105.1 C91.1@96.929,105.504
  Top Layer w0.4: C91.1@96.413,104.988 U13.3@96.413,102.854 U13.2@97.063,102.854
  Top Layer w0.6: L9.1@95.6,108.7 95.6,108.55 95.65,108.5 96.004,108.5 96.594,107.91 96.594,107.291 C92.1@96.929,106.956 C91.1@96.929,105.504 ; C91.1@96.525,105.1 R143.1@98,105.1
VISOOUT: C153.1 C154.1 C155.1 FB17.1 U23.12 U23.13 | length 14.1
  Top Layer w0.4: C155.1@278.25,17.7 278.404,17.854 280.354,17.854 280.4,17.9 281.2,17.9 281.55,18.25 281.65,18.25 C153.1@281.75,18.35 ; C153.1@281.75,18.45 281.833,18.533 282.233,18.533 283.25,19.55 U23.12@283.25,22.05 ; U23.13@284.52,22.05 284.541,22.029 284.541,20.703 285.694,19.55 FB17.1@287.35,19.55
  Top Layer w0.6: U23.12@283.25,22.05 U23.13@284.52,22.05
VP_CAN: C149.1 C150.1 C151.1 D18.2 FB17.2 J11.2 U23.20 | length 69.6
  Top Layer w0.2: D18.2@286.25,16.35 288.15,18.25 FB17.2@288.15,19.55
  Top Layer w0.4: FB17.2@288.15,19.55 289.275,19.55 289.925,18.9 C151.1@290.25,18.9 292.1,18.9 C150.1@292.25,19.05 C149.1@293.65,19.05 ; U23.20@293.41,22.05 293.41,19.59 293.75,19.25 C149.1@293.75,19.15
  Top Layer w0.5: J11.2@250.94,10.43 250.94,9.061 255,5 285.695,5 295.1,14.405 295.1,18.4 294.35,19.15 C149.1@293.75,19.15
VP_CAN_SUBD: J1.9 J11.1 | length 18.6
  Top Layer w0.5: J11.1@253.861,12.97 253.861,10.981 257.823,7.018 267.211,7.018 268.273,8.08 J1.9@268.345,8.08
pads on no net: FID1.1 FID2.1 FID3.1 J1.1 J1.8 J2.2 J2.3 J2.4 J2.5 J3.2 J3.3 J3.4 J3.5 J4.3 J5.2 J5.3 J5.4 J5.5 J6.3 J7.2 J7.3 J7.4 J7.5 J8.2 J8.3 J8.4 J8.5 J9.2 J9.3 J9.4 J9.5 J10.2 J10.3 J10.4 J10.5 J12.1 J12.2 J12.3 J12.4 J12.5 J12.6 J12.8 J12.23 J12.32 J12.34 J12.41 J12.43 J12.44 J12.45 J12.66 J12.85 J12.103 J12.105 J12.113 J12.114 J12.115 J12.116 J12.117 J12.118 J12.119 J12.120 J12.181 J12.182 J12.185 J12.186 J16.MH1 J16.MH2 J21.3 LBL1.0 MP1. MP1.1 MP2. MP2.1 MP3. MP3.1 MP4. MP5. MP5.1 MP6. MP7. MP7.1 MP8. MP8.1 MP9. MP9.1 MP10. MP10.1 MP11. MP11.1 MP12. MP13. MP13.1 MP14. MP14.1 MP15. MP15.1 Q1.0 Q2.0 Q3.0 R86.1 RN1.1 RN1.2 RN1.3 RN1.7 RN1.8 RN2.1 RN2.2 RN2.3 RN2.7 RN2.8 RN3.1 RN3.2 RN3.3 RN3.7 RN3.8 U1.2 U2.8 U2.10 U4.8 U4.10 U5.8 U5.10 U6.8 U6.10 U11.7 U11.8 U11.12 U11.13 U11.15 U20.9 U21.2 U22.7@149.05,16.376 U22.7@149.05,17.276 U23.2 U23.7 U23.14 U24.3 U25.3
copper on no net:
  other v1: 180.729,14.35 180.104,14.85 181.354,14.85 180.729,15.35 166.283,26.069 167.283,26.069 166.283,26.569 167.283,26.569 166.283,27.069 167.283,27.069

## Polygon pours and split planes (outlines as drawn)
NetL12_8 on Layer 2 "LAYER_2_NETL12_8_P089" (solid, remove dead copper, pour order 89): 26 vertices, not listed, extent 159,237 288,270
GND on Layer 2 "NONET_L-01_P-001" (solid, pour order 312): 26 vertices, not listed, extent 32.1,0.6 299.9,121
VDC-_REF on Layer 2 "Layer 2-VDC-_REF" (solid, pour order 359): 50 vertices, not listed, extent 1,1 270,297
GND on Layer 2 "NONET_L-01_P-001" (solid, pour order 313): 42 vertices, not listed, extent 92.9,72.7 299.7,275.5
PCC_N on Layer 2 "LAYER_2_PCC_N_P375" (solid, remove dead copper, pour order 375): 263,273 263,293 270,293 270,273
PCC_L1 on Layer 2 "LAYER_2_PCC_L1_P374" (solid, remove dead copper, pour order 374): 243,277 243,293 251,293 251,282 256,282 256,277
PCC_L2 on Layer 2 "LAYER_2_PCC_L2_P373" (solid, remove dead copper, pour order 373): 224,277 224,293 231,293 231,280 231,277 225,277
PCC_L3 on Layer 2 "LAYER_2_PCC_L3_P371" (solid, remove dead copper, pour order 371): 211,277 204,284 204,292 211,292 211,283 214,280 214,277
NetC213_N_2 on Layer 2 "NONET_L-01_P-001" (solid, pour order 343): 83.7,57.5 86.6,57.5 86.9,57.2 86.9,54.5 86.4,54 83.5,54 83.2,54.3 83.2,57
GND_S1_GaN_N on Layer 2 "NONET_L-01_P-001" (solid, pour order 322): 107.629,69.559 107.629,59.059 106.129,57.559 97.029,57.559 96.129,58.459 96.129,71.059 96.954,71.884 105.304,71.884
GND_S1_GaN_L3 on Layer 2 "NONET_L-01_P-001" (solid, pour order 321): 258.741,97.629 269.241,97.629 270.741,96.129 270.741,87.029 269.841,86.129 257.241,86.129 256.416,86.954 256.416,95.304
GND_S1_GaN_L1 on Layer 2 "NONET_L-01_P-001" (solid, pour order 320): 90.641,140.729 101.141,140.729 102.641,139.229 102.641,130.129 101.741,129.229 89.141,129.229 88.316,130.054 88.316,138.404
GND_S1_GaN_L2 on Layer 2 "NONET_L-01_P-001" (solid, pour order 319): 174.9,125.7 185.4,125.7 186.9,124.2 186.9,115.1 186,114.2 173.4,114.2 172.575,115.025 172.575,123.375
GRID_GND_1 on Layer 2 "LAYER_2_GRID_GND_1_P124" (solid, remove dead copper, pour order 124): 82,296 82,300 31,300 31,296 35,292 44,292 48,296
GND_S4_GaN_L2 on Layer 2 "LAYER_2_GND_S4_GAN_L2_P214" (solid, remove dead copper, pour order 214): 126.115,149.5 130,149.5 133,152.5 133,156 131.5,157.5 127,157.5 119.5,150 119.5,126.5 116,123 116,114.5 130.5,114.5 130.5,123 122.5,131 122.5,145.885
GND_S3_GaN_L2 on Layer 2 "LAYER_2_GND_S3_GAN_L2_P215" (solid, remove dead copper, pour order 215): 152.817,115.5 152.817,120.727 151.01,122.534 146,122.534 146,123.489 144.989,124.5 138.879,124.5 138.879,135.17 138.281,135.768 134.245,135.768 130.469,131.992 130.469,126.054 132.023,124.5 132.023,115.5
GND_S2_GaN_L2 on Layer 2 "LAYER_2_GND_S2_GAN_L2_P216" (solid, remove dead copper, pour order 216): 150,128.5 150,137.5 157,137.5 157,134.5 159,132.5 159,125.5 167.979,125.5 170,123.479 170,115.5 169,114.5 157,114.5 156,115.5 156,126 154.5,127.5 151,127.5
NetC213_L2_1 on Layer 2 "LAYER_2_NETC213_L2_1_P217" (solid, remove dead copper, pour order 217): 18 vertices, not listed, extent 130,135.5 177,149.5
NetC213_L2_2 on Layer 2 "LAYER_2_NETC213_L2_2_P218" (solid, remove dead copper, pour order 218): 171,149.5 172.5,148 172.5,145.5 162,145.5 161.5,146 161.5,155.5 165.2,155.5 165.2,151.3 167,149.5
12V on Layer 2 "NONET_L-01_P-001" (solid, pour order 289): 146.786,13.043 161.857,13.043 163.3,11.6 163.3,3.6 161.1,1.4 147.1,1.4 145.8,2.7 145.8,12.056
+12V_OUT on Layer 2 "NONET_L-01_P-001" (solid, pour order 286): 168,12.7 180.9,12.7 180.9,5.3 177.9,2.3 165.6,2.3 163.5,4.4 163.5,8.2
5V on Layer 2 "NONET_L-01_P-001" (solid, pour order 292): 154.4,29.4 170,29.4 172.1,27.3 172.1,18.191 170.009,16.1 154.2,16.1 151.6,18.7 151.6,26.6
+12V_OUT on Layer 2 "NONET_L-01_P-001" (solid, pour order 288): 180.9,7.4 183.8,4.5 183.8,2.6 183.5,2.3 177.7,2.3 177.7,7.4
NetC213_L3_2 on Layer 2 "LAYER_2_NETC213_L3_2_P262" (solid, remove dead copper, pour order 262): 255,121.5 256.5,120 256.5,117.5 246,117.5 245.5,118 245.5,127.5 249.6,127.5 249.6,122.9 251,121.5
NetC213_L3_1 on Layer 2 "LAYER_2_NETC213_L3_1_P261" (solid, remove dead copper, pour order 261): 18 vertices, not listed, extent 214,107.5 261,121.5
GND_S2_GaN_L3 on Layer 2 "LAYER_2_GND_S2_GAN_L3_P260" (solid, remove dead copper, pour order 260): 234,100.5 234,109.5 241,109.5 241,106.5 243,104.5 243,97.5 251.979,97.5 254,95.479 254,87.5 253,86.5 241,86.5 240,87.5 240,98 238.5,99.5 235,99.5
GND_S3_GaN_L3 on Layer 2 "LAYER_2_GND_S3_GAN_L3_P259" (solid, remove dead copper, pour order 259): 236.817,87.5 236.817,92.727 235.01,94.534 230,94.534 230,95.489 228.989,96.5 222.879,96.5 222.879,107.17 222.281,107.768 218.245,107.768 214.469,103.992 214.469,98.054 216.023,96.5 216.023,87.5
GND_S4_GaN_L3 on Layer 2 "LAYER_2_GND_S4_GAN_L3_P258" (solid, remove dead copper, pour order 258): 210.115,121.5 214,121.5 217,124.5 217,128 215.5,129.5 211,129.5 203.5,122 203.5,98.5 200,95 200,86.5 214.5,86.5 214.5,95 206.5,103 206.5,117.885
NetC213_L1_2 on Layer 2 "LAYER_2_NETC213_L1_2_P178" (solid, remove dead copper, pour order 178): 87,164.5 88.5,163 88.5,160.5 78,160.5 77.5,161 77.5,170.5 80.5,170.5 80.5,167 83,164.5
NetC213_L1_1 on Layer 2 "LAYER_2_NETC213_L1_1_P177" (solid, remove dead copper, pour order 177): 18 vertices, not listed, extent 46,150.5 93,164.5
GND_S2_GaN_L1 on Layer 2 "LAYER_2_GND_S2_GAN_L1_P176" (solid, remove dead copper, pour order 176): 66,143.5 66,152.5 73,152.5 73,149.5 75,147.5 75,140.5 83.979,140.5 86,138.479 86,130.5 85,129.5 73,129.5 72,130.5 72,141 70.5,142.5 67,142.5
GND_S3_GaN_L1 on Layer 2 "LAYER_2_GND_S3_GAN_L1_P175" (solid, remove dead copper, pour order 175): 68.817,130.5 68.817,135.727 67.01,137.534 62,137.534 62,138.489 60.989,139.5 54.879,139.5 54.879,150.17 54.281,150.768 50.245,150.768 46.469,146.992 46.469,141.054 48.023,139.5 48.023,130.5
GND_S4_GaN_L1 on Layer 2 "LAYER_2_GND_S4_GAN_L1_P174" (solid, remove dead copper, pour order 174): 42.115,164.5 46,164.5 49,167.5 49,171 47.5,172.5 43,172.5 35.5,165 35.5,141.5 32,138 32,129.5 46.5,129.5 46.5,138 38.5,146 38.5,160.885
+5VISO_PCC on Layer 2 "NONET_L-01_P-001" (solid, pour order 144): 103.009,266.3 139.6,266.3 140.1,265.8 140.1,259.826 139.774,259.5 103.5,259.5 102.6,260.4 102.6,265.891
V_PCC_L2 on Layer 2 "Layer 2-V_PCC_L2" (solid, remove dead copper, pour order 121): 29 vertices, not listed, extent 78,252 200,299
I_PCC_L2+ on Layer 2 "LAYER_2_I_PCC_L2+_P065" (solid, remove dead copper, pour order 65): 17 vertices, not listed, extent 28.5,267.5 73,286
GND_S4_GaN_N on Layer 2 "LAYER_2_GND_S4_GAN_N_P000" (solid, remove dead copper, pour order 0): 72,11.115 72,15 69,18 65.5,18 64,16.5 64,12 71.5,4.5 95,4.5 98.5,1 107,1 107,15.5 98.5,15.5 90.5,7.5 75.615,7.5
NetC213_N_1 on Layer 2 "LAYER_2_NETC213_N_1_P012" (solid, remove dead copper, pour order 12): 18 vertices, not listed, extent 72,15 86,62
NetC213_N_2 on Layer 2 "LAYER_2_NETC213_N_2_P027" (solid, remove dead copper, pour order 27): 72,56 73.5,57.5 76,57.5 76,47 75.5,46.5 66,46.5 66,49.9 69.9,49.9 72,52
GND_S2_GaN_N on Layer 2 "LAYER_2_GND_S2_GAN_N_P005" (solid, remove dead copper, pour order 5): 93,35 84,35 84,42 87,42 89,44 96,44 96,52.979 98.021,55 106,55 107,54 107,42 106,41 95.5,41 94,39.5 94,36
GND_S3_GaN_N on Layer 2 "LAYER_2_GND_S3_GAN_N_P004" (solid, remove dead copper, pour order 4): 106,37.817 100.773,37.817 98.966,36.01 98.966,31 98.011,31 97,29.989 97,23.879 86.33,23.879 85.732,23.281 85.732,19.245 89.508,15.469 95.446,15.469 97,17.023 106,17.023
GND on Bottom Layer "NONET_L-01_P-001" (solid, pour order 310): 30 vertices, not listed, extent 32.1,0.6 299.9,121
12V on Bottom Layer "NONET_L-01_P-001" (solid, pour order 290): 161,13.1 166.6,7.5 249.9,7.5 250.6,6.8 250.6,1.2 249.8,0.4 147,0.4 145.4,2 145.4,11.8 146.7,13.1
I_PCC_N+ on Bottom Layer "Bottom Layer-I_PCC_N+" (solid, pour order 358): 33 vertices, not listed, extent 0.5,94.5 59,289
GRID_GND_1 on Bottom Layer "BOTTOM_LAYER_GRID_GND_1_P125" (solid, remove dead copper, pour order 125): 31.2,296.1 31.2,299.6 43.6,299.6 43.6,292 35.3,292
V_PCC_N on Bottom Layer "Bottom Layer-V_PCC_N" (solid, remove dead copper, pour order 123): 27 vertices, not listed, extent 38,263 149,299
VDC-_REF on Bottom Layer "BOTTOM_LAYER_VDC-_REF_P377" (solid, remove dead copper, pour order 377): 100,179 103,179 113,169 113,143 112,142 107,142 102,147 102,167 100,169
VDC-_REF on Bottom Layer "BOTTOM_LAYER_VDC-_REF_P376" (solid, remove dead copper, pour order 376): 197,127 197,161 194,164 185,164 185,145 188,142 188,127
PCC_L3 on Bottom Layer "BOTTOM_LAYER_PCC_L3_P367" (solid, remove dead copper, pour order 367): 204.082,291.109 204.082,284.082 204,284 211,277 214,277 214,281 213,281 211,283 211,290 210,291 204,291
PCC_L2 on Bottom Layer "BOTTOM_LAYER_PCC_L2_P366" (solid, remove dead copper, pour order 366): 231,283 234.5,283 234.5,276 225,276 224,277 224,292 230,292 230,284
PCC_L1 on Bottom Layer "BOTTOM_LAYER_PCC_L1_P365" (solid, remove dead copper, pour order 365): 244,292 250,292 250,282 251,281 256,281 256,277 246,277 244,279
PCC_N on Bottom Layer "BOTTOM_LAYER_PCC_N_P364" (solid, remove dead copper, pour order 364): 264,276 270,276 270,292 264,292
NetC213_L3_2 on Bottom Layer "NONET_L-01_P-001" (solid, pour order 357): 253.1,110.6 256.5,110.6 256.5,107.1 256.4,107 253.1,107
NetC213_L3_2 on Bottom Layer "NONET_L-01_P-001" (solid, pour order 356): 253,121 255.5,121 256.5,120 256.5,117.3 253,117.3
NetC213_L3_1 on Bottom Layer "NONET_L-01_P-001" (solid, pour order 355): 215.7,110.8 218.5,110.8 218.5,107.9 217.6,107 215.7,107
NetC213_L3_1 on Bottom Layer "NONET_L-01_P-001" (solid, pour order 354): 216.264,121.5 220.2,121.5 220.3,121.4 220.3,117.2 215.3,117.2 214.9,117.6 214.9,120.2
NetC213_N_2 on Bottom Layer "NONET_L-01_P-001" (solid, pour order 353): 73.5,57.5 76.4,57.5 76.7,57.2 76.7,54.1 72.7,54.1 72.5,54.3 72.5,56.5
NetC213_N_2 on Bottom Layer "NONET_L-01_P-001" (solid, pour order 352): 87,57.4 87,54.1 86.9,54 82.9,54 82.9,57.4
NetC213_L2_2 on Bottom Layer "NONET_L-01_P-001" (solid, pour order 351): 169.1,138.3 172.1,138.3 172.1,135.1 169.1,135.1
NetC213_L2_2 on Bottom Layer "NONET_L-01_P-001" (solid, pour order 350): 169.1,148.7 171.6,148.7 172.2,148.1 172.2,145.4 172.1,145.3 169.1,145.3
NetC213_L2_1 on Bottom Layer "NONET_L-01_P-001" (solid, pour order 349): 131.4,138.8 134.5,138.8 134.5,136 133.5,135 131.4,135
NetC213_L2_1 on Bottom Layer "NONET_L-01_P-001" (solid, pour order 348): 132.2,149 135.6,149 135.6,145.2 131.6,145.2 131.6,148.4
NetC213_L1_2 on Bottom Layer "NONET_L-01_P-001" (solid, pour order 347): 85,153.4 88.1,153.4 88.3,153.2 88.3,149.8 85,149.8
NetC213_L1_1 on Bottom Layer "NONET_L-01_P-001" (solid, pour order 346): 47.6,153.8 50.4,153.8 50.5,153.7 50.5,151.1 49.4,150 47.6,150
NetC213_L1_1 on Bottom Layer "NONET_L-01_P-001" (solid, pour order 345): 48.4,164.1 51.5,164.1 52.6,163 52.6,160.1 47.5,160.1 47.3,160.3 47.3,162.9
NetC213_L1_2 on Bottom Layer "NONET_L-01_P-001" (solid, pour order 344): 85,164 87.5,164 88.5,163 88.4,162.9 88.4,160.6 88.3,160.5 85,160.5
NetC213_N_1 on Bottom Layer "NONET_L-01_P-001" (solid, pour order 342): 82.2,15 82.231,14.969 86.5,14.969 86.5,16.169 86.369,16.3 82.2,16.3
NetC213_N_1 on Bottom Layer "NONET_L-01_P-001" (solid, pour order 341): 73,19.6 85.4,19.6 86.5,18.5 86.5,16.169 73.331,16.169 73,16.5
VDC+ on Bottom Layer "NONET_L-01_P-001" (solid, pour order 340): 67.8,63.3 59.3,63.3 58.5,62.5 58.5,60.7 67.8,60.7
NetC213_N_2 on Bottom Layer "NONET_L-01_P-001" (solid, pour order 339): 77.9,57.3 82.6,57.3 82.6,54.3 77.9,54.3
NetC213_N_1 on Bottom Layer "NONET_L-01_P-001" (solid, pour order 338): 59.3,35 67.2,35 67.2,33.2 59.3,33.2
NetC213_N_2 on Bottom Layer "NONET_L-01_P-001" (solid, pour order 337): 60.1,40.8 60.2,40.7 66.5,40.7 66.5,38.8 58.6,38.8 58.2,39.2 58.2,40.8
NetC213_L3_1 on Bottom Layer "NONET_L-01_P-001" (solid, pour order 336): 214,111.4 215.8,111.4 215.8,107 214.9,106.1 213.8,106.1 213.8,107.1 214,107.3
NetC213_L3_2 on Bottom Layer "NONET_L-01_P-001" (solid, pour order 335): 253.7,115.8 256,115.8 256.2,115.6 256.2,111.4 253.8,111.4 253.7,111.5
VDC+ on Bottom Layer "NONET_L-01_P-001" (solid, pour order 334): 259.8,133.7 261.5,133.7 261.5,126.5 262.1,125.9 261.9,125.7 259.8,125.7
NetC213_L3_2 on Bottom Layer "NONET_L-01_P-001" (solid, pour order 333): 238.2,134.3 240.3,134.3 240.3,128.1 239.2,127 238.2,127
NetC213_L3_1 on Bottom Layer "NONET_L-01_P-001" (solid, pour order 332): 232.2,134.3 234,134.3 234,125.5 233.8,125.3 232.2,125.3
NetC213_L2_1 on Bottom Layer "NONET_L-01_P-001" (solid, pour order 331): 130.2,139.2 131.2,139.2 131.2,134.2 131,134 130.1,134 130.1,139.1
NetC213_L2_2 on Bottom Layer "NONET_L-01_P-001" (solid, pour order 330): 169.6,144.1 172.2,144.1 172.2,139.4 171.9,139.1 169.6,139.1
VDC+ on Bottom Layer "NONET_L-01_P-001" (solid, pour order 329): 175.5,161.7 177.5,161.7 177.5,153.7 175.6,153.7 175.5,153.8
NetC213_L2_2 on Bottom Layer "NONET_L-01_P-001" (solid, pour order 328): 154.2,162.5 156,162.5 156,155.5 155.5,155 154,155 154,162.3
NetC213_L2_1 on Bottom Layer "NONET_L-01_P-001" (solid, pour order 327): 148,162.4 150,162.4 150,153.7 149.8,153.5 148,153.5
